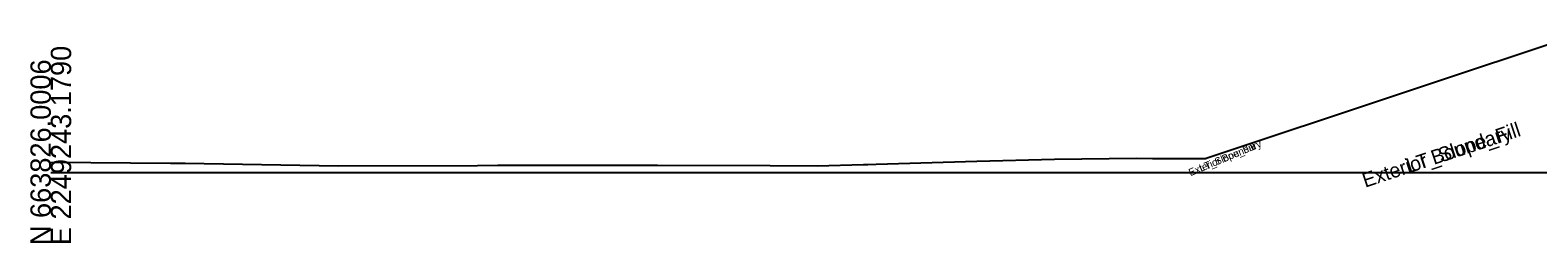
# Model space of a CAD drawing. Extents: x -26 to 2603, y -10 to 9566.
# Drawn here: x 997.2 to 1204.6, y 8490.3 to 8519.6 of the extents above; entities that cross this region are included whole.
import ezdxf

# ---------------------------------------------------------------- set-up
doc = ezdxf.new("R2010")
doc.units = 0
for name, color, linetype in [('Default', 7, 'Continuous'), ('Exist Cross Section Cell', 7, 'Continuous'), ('Exist XS Ground Line', 7, 'Continuous'), ('Scratch_Level_9', 7, 'Continuous')]:
    doc.layers.add(name, color=color, linetype=linetype)

msp = doc.modelspace()

# ---------------------------------------------------------------- linework, layer by layer
at = {"layer": 'Exist Cross Section Cell'}
msp.add_line((1000, 8500), (1300, 8500), dxfattribs=at)
at = {"layer": 'Exist XS Ground Line'}
for p, q in [((1000, 8501.44), (1016.49, 8501.3)), ((1016.49, 8501.3), (1017.57, 8501.3)), ((1017.57, 8501.3), (1018.47, 8501.28)), ((1018.47, 8501.28), (1039.54, 8500.95)), ((1105.44, 8500.95), (1111.8, 8501.14)), ((1111.8, 8501.14), (1112.42, 8501.14)), ((1112.42, 8501.14), (1113.57, 8501.17)), ((1113.57, 8501.17), (1127.41, 8501.56)), ((1127.41, 8501.56), (1138.08, 8501.85)), ((1138.08, 8501.85), (1149.37, 8502)), ((1149.37, 8502), (1151.59, 8501.94)), ((1151.59, 8501.94), (1158.63, 8501.94)), ((1158.63, 8501.94), (1158.95, 8501.95)), ((1039.54, 8500.95), (1058.73, 8501)), ((1058.73, 8501), (1061.51, 8501.02)), ((1061.51, 8501.02), (1064.85, 8501.02)), ((1064.85, 8501.02), (1083.47, 8501.02)), ((1083.47, 8501.02), (1098.98, 8500.96)), ((1098.98, 8500.96), (1105.44, 8500.95))]:
    msp.add_line(p, q, dxfattribs=at)
msp.add_lwpolyline([(1212.05, 8519.65), (1158.95, 8501.95)], dxfattribs=at)

# ---------------------------------------------------------------- texts
at = {"layer": 'Default'}
msp.add_text('-', height=0.0001, dxfattribs=at).set_placement((1000, 8500))
msp.add_text('-', height=0.0001, dxfattribs=at).set_placement((1000, 8500))
msp.add_text('-', height=0.0001, dxfattribs=at).set_placement((1000, 8500))
msp.add_text('-', height=0.0001, dxfattribs=at).set_placement((1000, 8500))
msp.add_text('-', height=0.0001, dxfattribs=at).set_placement((1000, 8500))
at = {"layer": 'Exist Cross Section Cell'}
for s, p in [('E 2249243.1790', (1002.8, 8490)), ('N 663826.0006', (1000, 8490))]:
    msp.add_text(s, height=2.8, rotation=90, dxfattribs=at).set_placement(p)
at = {"layer": 'Scratch_Level_9'}
for s, height, rotation, p in [('Exterior Boundary', 2, 18.4332, (1180.85, 8497.91)), ('Exterior Boundary', 2, 18.4332, (1180.85, 8497.91)), ('LT_Slope_Fill', 2, 18.4332, (1186.9, 8499.92)), ('LT_Slope_Fill', 2, 18.4332, (1186.9, 8499.92)), ('Exterior Boundary', 1, 22.5575, (1156.81, 8499.5)), ('LT_Slope_Fill', 1, 22.5575, (1158.27, 8500.11))]:
    msp.add_text(s, height=height, rotation=rotation, dxfattribs=at).set_placement(p)

doc.saveas('drawing.dxf')
